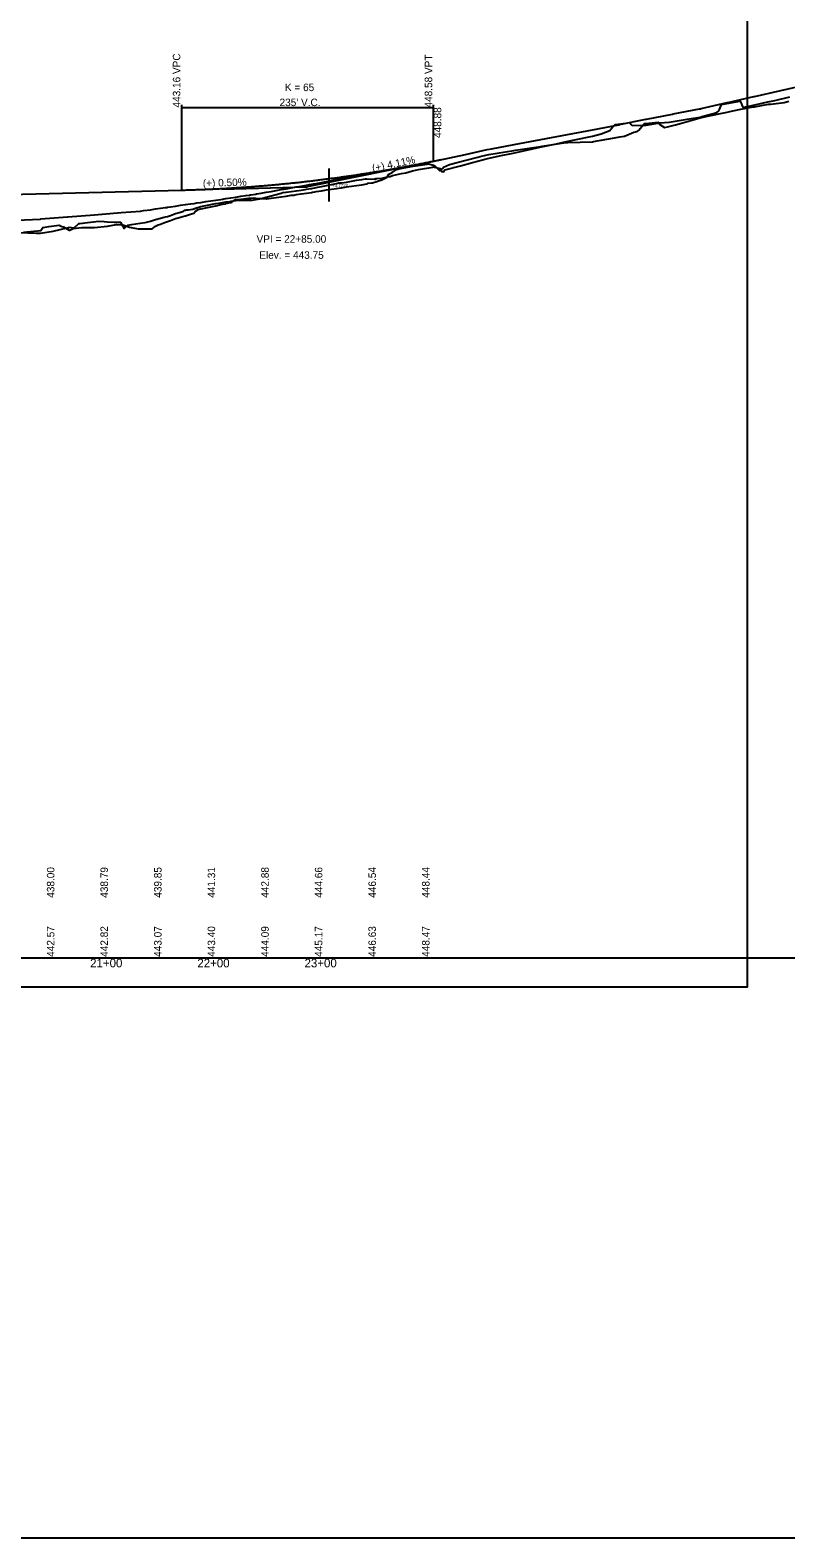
# Model space of a CAD drawing. Extents: x 2060925 to 2067820, y 1049917 to 1052773.
# Drawn here: x 2065865 to 2066571, y 1050573 to 1051979 of the extents above; entities that cross this region are included whole.
import ezdxf

# ---------------------------------------------------------------- set-up
doc = ezdxf.new("R2010")
doc.units = 0
for name, color, linetype in [('BR_EXIST_GROUND_LT', 7, 'Continuous'), ('BR_EXIST_GROUND_RT', 7, 'Continuous'), ('BR_USER NOTES', 7, 'Continuous'), ('RD_DDB_GradeTX', 7, 'Continuous'), ('RD_DDB_Profile_EX', 7, 'Continuous'), ('RD_DDB_Profile_Lbl', 7, 'Continuous'), ('RD_DDB_Profile_PR', 7, 'Continuous'), ('RD_DDB_StaTX', 7, 'Continuous'), ('RD_DDB_StripGrade', 7, 'Continuous'), ('RD_DDB_VCLbl', 7, 'Continuous'), ('RD_GPK_Profile_Cell', 7, 'Continuous'), ('RD_SHT_IplotShp', 7, 'Continuous'), ('RD_SHT_ShtClip', 7, 'Continuous')]:
    doc.layers.add(name, color=color, linetype=linetype)

msp = doc.modelspace()

# ---------------------------------------------------------------- linework, layer by layer
at = {"layer": 'BR_EXIST_GROUND_LT'}
msp.add_lwpolyline([(2065859.4, 1051790.7), (2065875.6, 1051792.2), (2065877.2, 1051795), (2065883, 1051796), (2065892.6, 1051797.3), (2065895.1, 1051795.9), (2065896.7, 1051795.6), (2065901.8, 1051792.4), (2065902.6, 1051792.4), (2065905.5, 1051794), (2065913.8, 1051794.9), (2065925.4, 1051795.1), (2065937.8, 1051796.1), (2065946.2, 1051797.7), (2065952, 1051797.6), (2065958.3, 1051795.4), (2065966.3, 1051793.8), (2065977.7, 1051793.9), (2065979.4, 1051793.9), (2065982.5, 1051796.2), (2065984.9, 1051797.4), (2065987.1, 1051798.1), (2065991.7, 1051799.9), (2065996.4, 1051801.6), (2066001.1, 1051803.3), (2066002.2, 1051803.7), (2066005.8, 1051804.7), (2066010.2, 1051805.8), (2066010.5, 1051806), (2066014.3, 1051807.2), (2066015.2, 1051807.5), (2066018.1, 1051808.5), (2066019.9, 1051810.1), (2066022.1, 1051811.9), (2066024.6, 1051812.3), (2066026.5, 1051812.6), (2066029.3, 1051813.2), (2066034, 1051814.2), (2066038.7, 1051815.2), (2066043.4, 1051816.3), (2066047.4, 1051817.1), (2066047.7, 1051817.2), (2066048.1, 1051817.3), (2066052.3, 1051818.3), (2066052.8, 1051818.4), (2066053.6, 1051818.6), (2066056.3, 1051820.4), (2066056.6, 1051820.9), (2066057.5, 1051821), (2066062.1, 1051821.5), (2066066.8, 1051822), (2066069.1, 1051822.2), (2066071.5, 1051822.5), (2066074.3, 1051822.8), (2066075, 1051822.2), (2066076.2, 1051822.2), (2066080.9, 1051822), (2066083.4, 1051821.9), (2066085.7, 1051821.8), (2066086.1, 1051821.7), (2066090.3, 1051822.3), (2066095, 1051823), (2066099.7, 1051823.7), (2066104.4, 1051824.3), (2066109.1, 1051825), (2066110.5, 1051825.2), (2066111.4, 1051825.3), (2066113.8, 1051825.7), (2066118.5, 1051826.4), (2066123.2, 1051827), (2066127.9, 1051827.7), (2066128.9, 1051827.9), (2066131, 1051828.3), (2066132.5, 1051828.6), (2066137.2, 1051829.3), (2066141.9, 1051830), (2066146.6, 1051830.7), (2066151.3, 1051831.4), (2066155.4, 1051832), (2066156, 1051832.1), (2066160.7, 1051832.8), (2066165.4, 1051833.5), (2066170.1, 1051834.2), (2066174.8, 1051834.9), (2066179.5, 1051835.6), (2066179.8, 1051835.7), (2066180.8, 1051836.2), (2066184.2, 1051836.7), (2066184.9, 1051836.8), (2066188.9, 1051837.9), (2066189.7, 1051838.2), (2066192.7, 1051839.1), (2066193.6, 1051839.5), (2066198.6, 1051842), (2066200.1, 1051844.6), (2066203.4, 1051846.4), (2066207.3, 1051849.1), (2066210.6, 1051849.9), (2066222.8, 1051852.3), (2066235.8, 1051854.2), (2066237, 1051854.4), (2066241.7, 1051853.1), (2066242.9, 1051852.8), (2066247.7, 1051847.8), (2066250.4, 1051850.3), (2066251.3, 1051851.2), (2066256.7, 1051853.6), (2066262.7, 1051855.3), (2066283.1, 1051860.6), (2066285.2, 1051861.2), (2066291.9, 1051862.9), (2066293.4, 1051863.2), (2066316.9, 1051866.8), (2066318.4, 1051867.1), (2066341.9, 1051870.6), (2066343.3, 1051870.9), (2066365.4, 1051874.3), (2066367, 1051874.4), (2066390.2, 1051875), (2066391.1, 1051875.1), (2066410.6, 1051878.6), (2066415.8, 1051879.5), (2066419.9, 1051880.2), (2066428.8, 1051883.8), (2066431.8, 1051884.5), (2066433.9, 1051886), (2066434.5, 1051887.2), (2066438.2, 1051891.3), (2066438.7, 1051891.9), (2066440, 1051892), (2066451.5, 1051893.2), (2066452.9, 1051891.1), (2066457.3, 1051888.4), (2066460.1, 1051888.9), (2066467.7, 1051890.6), (2066473.2, 1051892.4), (2066490.5, 1051897.3), (2066497.6, 1051898.8), (2066515.7, 1051902.7), (2066518.2, 1051903.3), (2066527.1, 1051905.2), (2066540, 1051907.4), (2066540.9, 1051907.6), (2066541.3, 1051907.6), (2066554.4, 1051909.9), (2066556.5, 1051910.1), (2066569.1, 1051911.7), (2066573.2, 1051912.8)], dxfattribs=at)
at = {"layer": 'BR_EXIST_GROUND_RT'}
msp.add_lwpolyline([(2065855.3, 1051790.3), (2065871.3, 1051789.7), (2065875.3, 1051789.8), (2065886.9, 1051791.7), (2065900.1, 1051794.8), (2065901.4, 1051795.1), (2065901.9, 1051795.2), (2065906.5, 1051794.6), (2065910.8, 1051798.7), (2065911.7, 1051798.8), (2065919, 1051799.7), (2065924.5, 1051800.3), (2065929.4, 1051800.8), (2065934.7, 1051800.5), (2065937.3, 1051800.2), (2065943.8, 1051799.9), (2065944.7, 1051800), (2065947.1, 1051800.1), (2065949.8, 1051799.9), (2065953.2, 1051794), (2065956.6, 1051797.2), (2065960.1, 1051797.7), (2065968.1, 1051798.9), (2065972.7, 1051799.6), (2065977.7, 1051801), (2065982.4, 1051802.4), (2065987.1, 1051803.7), (2065990.5, 1051804.7), (2065991.7, 1051804.9), (2065993.6, 1051805.4), (2065995.6, 1051806), (2065996.4, 1051806.3), (2066001.1, 1051808), (2066005.8, 1051809.4), (2066008.5, 1051810.2), (2066009.5, 1051811.1), (2066010.5, 1051811.3), (2066011.3, 1051811.4), (2066013.2, 1051811.5), (2066015.2, 1051811.8), (2066017.4, 1051812.2), (2066019.9, 1051813), (2066023.7, 1051814.3), (2066024.6, 1051814.5), (2066029.3, 1051815.6), (2066034, 1051816.6), (2066035.4, 1051816.9), (2066038.7, 1051817.4), (2066043.4, 1051818.1), (2066048.1, 1051818.8), (2066052.1, 1051819.4), (2066052.8, 1051819.5), (2066057.5, 1051820.2), (2066060.3, 1051820.6), (2066062.1, 1051820.5), (2066066.8, 1051820.5), (2066071.5, 1051820.5), (2066072.5, 1051820.5), (2066075.6, 1051821), (2066076.2, 1051821.1), (2066079.8, 1051821.7), (2066080.9, 1051822), (2066085.6, 1051823.3), (2066090.3, 1051824.6), (2066095, 1051825.9), (2066099.7, 1051827.1), (2066101.1, 1051827.5), (2066104.4, 1051828), (2066109.1, 1051828.6), (2066113.8, 1051829.3), (2066118.5, 1051829.9), (2066122.1, 1051830.4), (2066123.2, 1051830.6), (2066127.5, 1051831.4), (2066127.9, 1051831.4), (2066128.4, 1051831.5), (2066132.5, 1051832.3), (2066133.9, 1051832.5), (2066137.2, 1051833.2), (2066141.9, 1051834.2), (2066146.6, 1051835.1), (2066151.3, 1051836.1), (2066153.5, 1051836.5), (2066156, 1051836.8), (2066160.7, 1051837.4), (2066162.3, 1051837.6), (2066165.4, 1051838.2), (2066170.1, 1051839), (2066174.8, 1051839.9), (2066178.3, 1051840.5), (2066179.5, 1051840.5), (2066184.4, 1051840.2), (2066186.9, 1051840.3), (2066187.5, 1051839.8), (2066188, 1051840.7), (2066188.9, 1051840.7), (2066193.8, 1051841), (2066200.2, 1051842.5), (2066201.5, 1051842.6), (2066203.5, 1051843.5), (2066211.9, 1051845.3), (2066215.9, 1051846), (2066222.2, 1051847.7), (2066227.7, 1051849.1), (2066241.2, 1051851.4), (2066241.5, 1051851.5), (2066242, 1051851.6), (2066242.8, 1051851.4), (2066248, 1051850), (2066249.4, 1051847.1), (2066251.5, 1051847), (2066252.3, 1051848.8), (2066267.1, 1051852.6), (2066278.1, 1051855.6), (2066287.6, 1051858.1), (2066291, 1051859.1), (2066303.3, 1051861.7), (2066316, 1051864.4), (2066330, 1051867.4), (2066341, 1051869.8), (2066356.6, 1051873.1), (2066365.9, 1051875.1), (2066373.5, 1051876.8), (2066390.3, 1051880.3), (2066398.2, 1051882.5), (2066406.4, 1051885.4), (2066407.3, 1051886.7), (2066409.2, 1051889), (2066411.7, 1051891.2), (2066421.3, 1051892.4), (2066424.9, 1051893), (2066426.3, 1051891.2), (2066427.2, 1051890), (2066440.3, 1051890.3), (2066453.1, 1051892.5), (2066461.8, 1051893.2), (2066478.6, 1051896.1), (2066482.3, 1051896.5), (2066490.7, 1051898), (2066492.2, 1051898.4), (2066499.3, 1051900.3), (2066506.1, 1051902.4), (2066508.1, 1051903.8), (2066508.6, 1051905.1), (2066510.6, 1051909.7), (2066527.5, 1051912.7), (2066527.9, 1051912.8), (2066528.8, 1051911), (2066529.9, 1051908.5), (2066530.5, 1051907.2), (2066534.4, 1051907.8), (2066534.7, 1051907.9), (2066553.6, 1051912.1), (2066560.2, 1051913.4), (2066574.2, 1051916.9)], dxfattribs=at)
at = {"layer": 'BR_USER NOTES'}
for p, q in [((2066144.1, 1051850), (2066144.1, 1051819.3)), ((2066139.1, 1051837.4), (2066144.1, 1051838.3))]:
    msp.add_line(p, q, dxfattribs=at)
at = {"layer": 'RD_DDB_GradeTX'}
for p in [(2066202.5, 1051848.9), (2066044.2, 1051830.8)]:
    msp.add_line(p, (2066124.1, 1051832.8), dxfattribs=at)
at = {"layer": 'RD_DDB_Profile_EX'}
msp.add_lwpolyline([(2065852.8, 1051801.8), (2065875.2, 1051802.9), (2065875.6, 1051803), (2065900.2, 1051804.9), (2065900.6, 1051804.9), (2065925.5, 1051806.9), (2065950.3, 1051808.9), (2065968.3, 1051810.3), (2065971.2, 1051810.7), (2065977.7, 1051811.6), (2065982.4, 1051812.3), (2065987.1, 1051813), (2065991.7, 1051813.7), (2065992.9, 1051813.8), (2065993.5, 1051813.9), (2065996.4, 1051814.3), (2066001.1, 1051815), (2066005.8, 1051815.7), (2066010.5, 1051816.4), (2066015.2, 1051817), (2066018.1, 1051817.4), (2066018.5, 1051817.5), (2066019.9, 1051817.7), (2066020.9, 1051817.9), (2066024.6, 1051818.4), (2066029.3, 1051819.1), (2066034, 1051819.8), (2066038.7, 1051820.5), (2066043.4, 1051821.2), (2066045.3, 1051821.5), (2066046.1, 1051821.6), (2066048.1, 1051821.9), (2066052.8, 1051822.6), (2066057.5, 1051823.4), (2066062.1, 1051824.1), (2066066.8, 1051824.8), (2066070.3, 1051825.3), (2066070.9, 1051825.4), (2066071.5, 1051825.5), (2066076.2, 1051826.2), (2066076.8, 1051826.3), (2066080.9, 1051827), (2066085.6, 1051827.9), (2066090.3, 1051828.7), (2066095, 1051829.5), (2066099.7, 1051830.3), (2066101, 1051830.6), (2066102.2, 1051830.8), (2066104.4, 1051831.1), (2066109.1, 1051832), (2066113.8, 1051832.8), (2066118.5, 1051833.6), (2066123.2, 1051834.4), (2066126.2, 1051835), (2066127.9, 1051835.3), (2066128.9, 1051835.5), (2066129.9, 1051835.6), (2066132.5, 1051836.1), (2066137.2, 1051837), (2066141.9, 1051837.9), (2066146.6, 1051838.8), (2066151.3, 1051839.7), (2066153.9, 1051840.2), (2066155.1, 1051840.4), (2066156, 1051840.5), (2066160.7, 1051841.4), (2066165.4, 1051842.3), (2066170.1, 1051843.2), (2066174.8, 1051844.1), (2066178.9, 1051844.9), (2066179.5, 1051845), (2066182.8, 1051845.6), (2066183.4, 1051845.7), (2066184.2, 1051845.9), (2066188.9, 1051846.7), (2066193.6, 1051847.5), (2066207.7, 1051850), (2066208.1, 1051850.1), (2066221.7, 1051852.5), (2066246.7, 1051857.9), (2066271.6, 1051863.2), (2066291.9, 1051867.6), (2066296, 1051868.3), (2066317, 1051872.3), (2066342, 1051877), (2066366.9, 1051881.7), (2066390.1, 1051886.1), (2066414.8, 1051890.9), (2066415.3, 1051891.1), (2066439.9, 1051895.9), (2066440.4, 1051896), (2066464.9, 1051900.8), (2066465.5, 1051900.9), (2066490.1, 1051905.7), (2066490.8, 1051905.8), (2066491.6, 1051906), (2066515.7, 1051911.5), (2066516.4, 1051911.7), (2066540.7, 1051917.2), (2066541.3, 1051917.3), (2066565.8, 1051922.9), (2066590.4, 1051928.5)], dxfattribs=at)
at = {"layer": 'RD_DDB_Profile_PR'}
for p, q in [((2066241.6, 1051856.9), (2066249.1, 1051858.5)), ((2065469.1, 1051816.4), (2066006.6, 1051829.8))]:
    msp.add_line(p, q, dxfattribs=at)
msp.add_spline([(2066006.6, 1051829.8), (2066011.3, 1051830), (2066016, 1051830.1), (2066020.7, 1051830.3), (2066025.4, 1051830.4), (2066030.1, 1051830.6), (2066034.8, 1051830.8), (2066039.5, 1051831.1), (2066044.2, 1051831.3), (2066048.9, 1051831.6), (2066053.6, 1051831.9), (2066058.3, 1051832.2), (2066063, 1051832.5), (2066067.7, 1051832.8), (2066072.4, 1051833.1), (2066077.1, 1051833.5), (2066081.8, 1051833.9), (2066086.5, 1051834.3), (2066091.2, 1051834.7), (2066095.9, 1051835.1), (2066100.6, 1051835.6), (2066105.3, 1051836), (2066110, 1051836.5), (2066114.7, 1051837), (2066119.4, 1051837.5), (2066124.1, 1051838.1), (2066128.8, 1051838.6), (2066133.5, 1051839.2), (2066138.2, 1051839.8), (2066142.9, 1051840.4), (2066147.6, 1051841), (2066152.3, 1051841.6), (2066157, 1051842.3), (2066161.7, 1051843), (2066166.4, 1051843.6), (2066171.1, 1051844.3), (2066175.8, 1051845.1), (2066180.5, 1051845.8), (2066185.2, 1051846.6), (2066189.9, 1051847.3), (2066194.6, 1051848.1), (2066199.3, 1051848.9), (2066204, 1051849.7), (2066208.7, 1051850.6), (2066213.4, 1051851.4), (2066218.1, 1051852.3), (2066222.8, 1051853.2), (2066227.5, 1051854.1), (2066232.2, 1051855), (2066236.9, 1051856), (2066241.6, 1051856.9)], degree=3, dxfattribs=at)
at = {"layer": 'RD_DDB_VCLbl'}
for p, q in [((2066006.6, 1051909.4), (2066006.6, 1051829.8)), ((2066006.6, 1051906.9), (2066241.6, 1051906.9)), ((2066241.6, 1051909.4), (2066241.6, 1051856.9))]:
    msp.add_line(p, q, dxfattribs=at)
at = {"layer": 'RD_GPK_Profile_Cell'}
msp.add_line((2064839.1, 1051114), (2067200.8, 1051114), dxfattribs=at)
at = {"layer": 'RD_SHT_IplotShp'}
msp.add_lwpolyline([(2064220, 1050573), (2067820, 1050573), (2067820, 1052773), (2064220, 1052773)], close=True, dxfattribs=at)
at = {"layer": 'RD_SHT_ShtClip'}
msp.add_lwpolyline([(2064734.6, 1052186.6), (2066534.6, 1052186.6), (2066534.6, 1051086.6), (2064734.6, 1051086.6)], close=True, dxfattribs=at)

# ---------------------------------------------------------------- texts
at = {"layer": 'BR_USER NOTES'}
msp.add_text('+3.7720', height=3, dxfattribs=at).set_placement((2066147.1, 1051832.7))
at = {"layer": 'RD_DDB_GradeTX'}
for s, rotation, p in [('(+) 4.11%', 11.6126, (2066185.3, 1051846.8)), ('(+) 0.50%', 1.4321, (2066026.7, 1051832.9))]:
    msp.add_text(s, height=7, rotation=rotation, dxfattribs=at).set_placement(p)
at = {"layer": 'RD_DDB_Profile_Lbl'}
msp.add_text('448.88', height=7, rotation=90, dxfattribs=at).set_placement((2066249.1, 1051878.5))
for s, p in [('VPI = 22+85.00', (2066076.7, 1051780.8)), ('Elev. = 443.75', (2066079.3, 1051765.8))]:
    msp.add_text(s, height=7, dxfattribs=at).set_placement(p)
at = {"layer": 'RD_DDB_StaTX'}
for s, p in [('21+00', (2065921.5, 1051105)), ('22+00', (2066021.5, 1051105)), ('23+00', (2066121.5, 1051105))]:
    msp.add_text(s, height=8, dxfattribs=at).set_placement(p)
at = {"layer": 'RD_DDB_StripGrade'}
for s, p in [('443.16 VPC', (2066005.6, 1051906.9)), ('448.58 VPT', (2066240.6, 1051906.9)), ('438.00', (2065888.1, 1051169.9)), ('438.79', (2065938.1, 1051169.9)), ('439.85', (2065988.1, 1051169.9)), ('441.31', (2066038.1, 1051169.9)), ('442.88', (2066088.1, 1051169.9)), ('444.66', (2066138.1, 1051169.9)), ('446.54', (2066188.1, 1051169.9)), ('448.44', (2066238.1, 1051169.9)), ('442.57', (2065888.1, 1051114.8)), ('442.82', (2065938.1, 1051114.8)), ('443.07', (2065988.1, 1051114.8)), ('443.40', (2066038.1, 1051114.8)), ('444.09', (2066088.1, 1051114.8)), ('445.17', (2066138.1, 1051114.8)), ('446.63', (2066188.1, 1051114.8)), ('448.47', (2066238.1, 1051114.8))]:
    msp.add_text(s, height=7, rotation=90, dxfattribs=at).set_placement(p)
at = {"layer": 'RD_DDB_VCLbl'}
for s, p in [('K = 65', (2066103.2, 1051922.2)), ("235' V.C.", (2066098.2, 1051908.2))]:
    msp.add_text(s, height=7, dxfattribs=at).set_placement(p)

doc.saveas('drawing.dxf')
